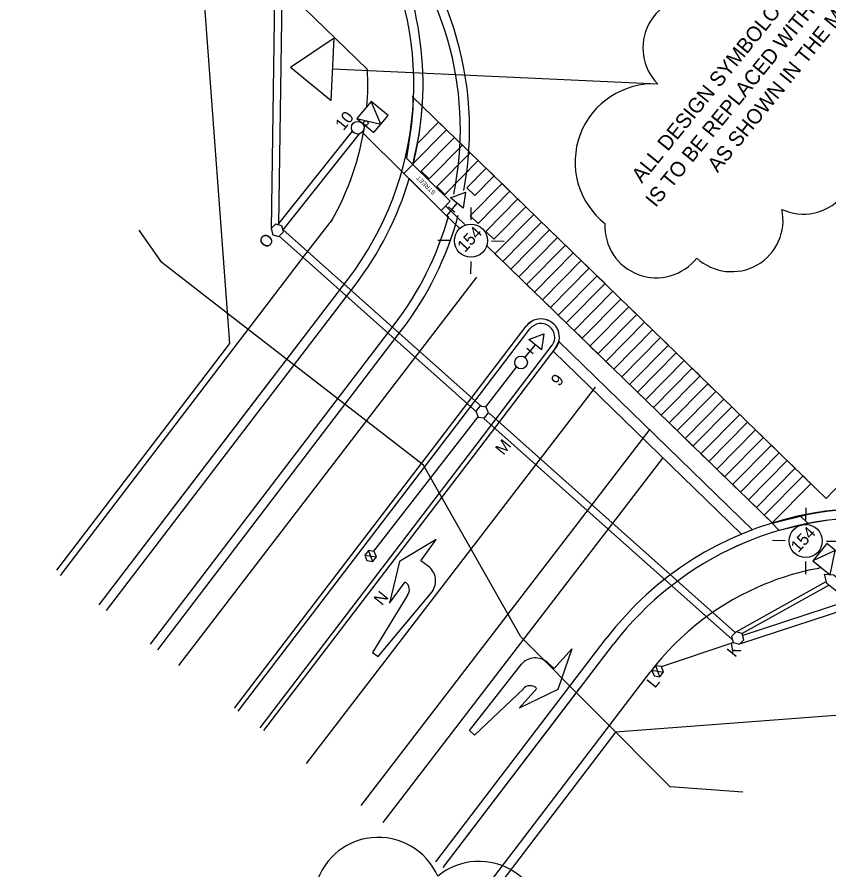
# Model space of a CAD drawing. Extents: x 592613 to 600223, y 4837996 to 4840103.
# Drawn here: x 592734.31 to 592778.42, y 4838979.64 to 4839025.97 of the extents above; entities that cross this region are included whole.
import ezdxf

# ---------------------------------------------------------------- set-up
doc = ezdxf.new("R2010")
doc.units = 0
for name, color, linetype in [('ENG_CURB-BACK', 7, 'Continuous'), ('ENG_CURBSTOP', 7, 'Continuous'), ('ENG_EPAVT', 7, 'Continuous'), ('ENG_LANEWAY', 7, 'Continuous'), ('ENG_LIMITS', 7, 'Continuous'), ('ENG_SH_RIPRAP', 7, 'Continuous'), ('ENG_SIDEWALK', 7, 'Continuous'), ('ENG_TX_TITLEBLOCK', 7, 'Continuous'), ('Level 1', 7, 'Continuous'), ('Level 12', 7, 'Continuous'), ('Level 9', 7, 'Continuous'), ('PMK_LANE', 7, 'Continuous'), ('ROW_ENG_ROW', 7, 'Continuous'), ('ROW_ENG_ROW BO', 7, 'Continuous'), ('TCS_100mm-NEW', 7, 'Continuous'), ('TCS_50mm-NEW', 7, 'Continuous'), ('TCS_ELEC-CHAMBER-NEW', 7, 'Continuous'), ('TCS_LUMINAIRE-NEW', 7, 'Continuous'), ('TCS_POLE-NEW', 7, 'Continuous'), ('TCS_PUSHBUTTON', 7, 'Continuous'), ('TCS_RADAR', 7, 'Continuous'), ('TCS_SIGN', 7, 'Continuous'), ('TCS_SIGNALHEAD', 7, 'Continuous')]:
    doc.layers.add(name, color=color, linetype=linetype)

msp = doc.modelspace()

# ---------------------------------------------------------------- linework, layer by layer
at = {"layer": 'ENG_CURB-BACK'}
for p, q in [((592738.776, 4838994.031), (592752.277, 4839011.713)), ((592741.558, 4838991.907), (592754.805, 4839009.256)), ((592758.431, 4839004.119), (592762.178, 4839009.026)), ((592759.304, 4839002.791), (592763.387, 4839008.138)), ((592746.327, 4838988.266), (592758.431, 4839004.119)), ((592747.519, 4838987.355), (592759.302, 4839002.787)), ((592757.455, 4838979.77), (592766.716, 4838991.9)), ((592759.442, 4838978.253), (592768.704, 4838990.383))]:
    msp.add_line(p, q, dxfattribs=at)
for centre, radius, start, end in [((592740.896, 4839019.876), 17.5, 348.3699, 40.5041), ((592738.367, 4839022.332), 17.5, 322.6377, 27.9119), ((592740.896, 4839019.876), 17.5, 322.6377, 344.4), ((592762.777, 4839008.574), 0.75, 324.4115, 142.9443), ((592780.625, 4838981.28), 17.5, 62.8455, 116.2063), ((592780.625, 4838981.28), 17.5, 113.9004, 142.6377)]:
    msp.add_arc(centre, radius, start, end, dxfattribs=at)
at = {"layer": 'ENG_CURBSTOP'}
msp.add_line((592777.297, 4838998.461), (592776.864, 4838998.883), dxfattribs=at)
for points in [[(592755.466, 4839018.314), (592755.822, 4839017.968), (592756.153, 4839019.562), (592756.288, 4839020.638), (592756.319, 4839021.125), (592756.319, 4839021.125), (592755.812, 4839021.617), (592755.814, 4839021.672), (592755.814, 4839020.962), (592755.733, 4839020.168)], [(592780.551, 4838998.78), (592779.535, 4838998.746), (592778.397, 4838998.637), (592777.421, 4838998.484), (592775.714, 4838998.071), (592775.331, 4838998.477), (592777.309, 4838998.972), (592777.839, 4838999.063), (592778.295, 4838999.128), (592778.96, 4838999.203), (592779.671, 4838999.255), (592780.218, 4838999.275), (592780.463, 4838999.279)]]:
    msp.add_lwpolyline(points, close=True, dxfattribs=at)
at = {"layer": 'ENG_EPAVT'}
for p, q in [((592739.174, 4838993.727), (592752.674, 4839011.409)), ((592741.956, 4838991.603), (592755.202, 4839008.953)), ((592758.279, 4839004.331), (592761.979, 4839009.177)), ((592759.45, 4839002.57), (592763.555, 4839007.946)), ((592746.128, 4838988.417), (592758.274, 4839004.325)), ((592747.718, 4838987.204), (592759.45, 4839002.57)), ((592757.057, 4838980.073), (592766.319, 4838992.203))]:
    msp.add_line(p, q, dxfattribs=at)
for centre, radius, start, end in [((592740.896, 4839019.876), 18, 349.35, 45.8289), ((592738.367, 4839022.332), 18, 345.9453, 28.6887), ((592738.367, 4839022.332), 18, 322.6377, 343.3725), ((592740.896, 4839019.876), 18, 322.6377, 344.9839), ((592762.775, 4839008.576), 1, 320.9502, 142.7929), ((592762.775, 4839008.576), 1, 320.9502, 142.7929), ((592762.777, 4839008.574), 1, 321.1016, 142.9443), ((592780.625, 4838981.28), 18, 62.5135, 142.6377)]:
    msp.add_arc(centre, radius, start, end, dxfattribs=at)
at = {"layer": 'ENG_LANEWAY'}
for p, q in [((592743.099, 4838990.747), (592759.299, 4839011.849)), ((592750.039, 4838985.418), (592765.735, 4839005.863)), ((592753.014, 4838983.135), (592768.709, 4839003.58)), ((592754.204, 4838982.221), (592769.388, 4839002))]:
    msp.add_line(p, q, dxfattribs=at)
at = {"layer": 'ENG_LIMITS'}
for p, q in [((592749.158, 4839023.247), (592751.537, 4839024.843)), ((592751.381, 4839021.441), (592751.537, 4839024.843)), ((592749.158, 4839023.247), (592751.381, 4839021.441)), ((592769.119, 4839022.334), (592751.459, 4839023.142))]:
    msp.add_line(p, q, dxfattribs=at)
for centre, radius, start, end in [((592771.108, 4839024.295), 2.793, 79.6053, 224.6053), ((592768.882, 4839018.089), 4.252, 86.7923, 231.7923), ((592777.034, 4839018.06), 2.793, 245.2392, 30.2392), ((592773.136, 4839014.931), 2.793, 227.2571, 12.2571), ((592769.041, 4839014.601), 2.793, 176.9654, 321.9654), ((592753.939, 4838977.886), 3.522, 23.5797, 168.5797), ((592759.41, 4838976.578), 3.523, 344.5454, 129.5454)]:
    msp.add_arc(centre, radius, start, end, dxfattribs=at)
at = {"layer": 'ENG_SH_RIPRAP'}
msp.add_lwpolyline([(592773.75, 4838983.869), (592769.802, 4838984.16), (592761.677, 4838992.304), (592756.39, 4839001.633), (592745.737, 4839009.864), (592742.175, 4839012.629), (592740.944, 4839014.402)], dxfattribs=at)
msp.add_lwpolyline([(592773.75, 4838983.869), (592769.802, 4838984.16), (592761.677, 4838992.304), (592756.39, 4839001.633), (592745.737, 4839009.864), (592742.175, 4839012.629), (592740.944, 4839014.402)], dxfattribs=at)
at = {"layer": 'ENG_SIDEWALK'}
for p, q in [((592753.347, 4839023.116), (592727.227, 4839048.491)), ((592749.952, 4839013.028), (592751.442, 4839014.981)), ((592736.673, 4838995.637), (592749.952, 4839013.028)), ((592738.776, 4838994.031), (592748.155, 4839006.314)), ((592757.455, 4838979.77), (592764.893, 4838989.512))]:
    msp.add_line(p, q, dxfattribs=at)
for centre, start, end in [((592738.367, 4839022.332), 355.3661, 2.9955), ((592738.367, 4839022.332), 330.2382, 351.4856), ((592780.625, 4838981.28), 100.1986, 113.33), ((592780.625, 4838981.28), 112.093, 142.6377)]:
    msp.add_arc(centre, 15, start, end, dxfattribs=at)
at = {"layer": 'Level 1'}
msp.add_line((592777.822, 4838996.891), (592777.881, 4838996.843), dxfattribs=at)
at = {"layer": 'Level 12'}
for p, q in [((592757.087, 4838997.598), (592755.094, 4838996.389)), ((592756.241, 4838996.439), (592757.087, 4838997.598)), ((592755.094, 4838996.389), (592754.55, 4838994.122)), ((592756.641, 4838996.147), (592756.241, 4838996.439)), ((592754.55, 4838994.122), (592755.396, 4838995.281)), ((592755.528, 4838994.565), (592753.626, 4838991.449)), ((592753.921, 4838991.233), (592756.859, 4838994.75)), ((592753.626, 4838991.449), (592753.921, 4838991.233)), ((592763.5, 4838990.573), (592764.456, 4838991.643)), ((592764.456, 4838991.643), (592763.692, 4838989.441)), ((592758.897, 4838987.212), (592761.719, 4838990.822)), ((592763.131, 4838990.902), (592763.5, 4838990.573)), ((592761.817, 4838989.483), (592759.17, 4838986.968)), ((592761.59, 4838988.433), (592762.545, 4838989.503)), ((592763.692, 4838989.441), (592761.59, 4838988.433)), ((592759.17, 4838986.968), (592758.897, 4838987.212))]:
    msp.add_line(p, q, dxfattribs=at)
for centre, radius, start, end in [((592756.051, 4838995.339), 1, 323.8506, 53.8728), ((592755.124, 4838994.86), 0.5, 323.8443, 53.8679), ((592762.464, 4838990.157), 1, 48.242, 138.2642), ((592762.19, 4838989.149), 0.5, 48.2469, 138.2706)]:
    msp.add_arc(centre, radius, start, end, dxfattribs=at)
at = {"layer": 'PMK_LANE'}
for p, q in [((592756.327, 4839021.131), (592778.275, 4838999.816)), ((592778.275, 4838999.816), (592797.765, 4839020.444)), ((592757.215, 4839020.268), (592756.078, 4839019.116)), ((592757.646, 4839019.85), (592757.215, 4839020.268)), ((592755.845, 4839018.026), (592757.646, 4839019.85)), ((592758.076, 4839019.432), (592756.267, 4839017.6)), ((592758.507, 4839019.014), (592758.076, 4839019.432)), ((592756.698, 4839017.182), (592758.507, 4839019.014)), ((592758.937, 4839018.596), (592757.123, 4839016.758)), ((592759.368, 4839018.178), (592758.937, 4839018.596)), ((592757.553, 4839016.34), (592759.368, 4839018.178)), ((592759.798, 4839017.76), (592758.744, 4839016.693)), ((592760.228, 4839017.342), (592759.798, 4839017.76)), ((592756.267, 4839017.6), (592756.698, 4839017.182)), ((592759.175, 4839016.274), (592760.228, 4839017.342)), ((592757.123, 4839016.758), (592757.553, 4839016.34)), ((592760.659, 4839016.924), (592758.924, 4839015.167)), ((592761.089, 4839016.506), (592760.659, 4839016.924)), ((592758.744, 4839016.693), (592759.175, 4839016.274)), ((592759.355, 4839014.749), (592761.089, 4839016.506)), ((592761.52, 4839016.088), (592759.781, 4839014.326)), ((592761.95, 4839015.67), (592761.52, 4839016.088)), ((592757.596, 4839015.716), (592758.672, 4839014.671)), ((592760.211, 4839013.908), (592761.95, 4839015.67)), ((592758.924, 4839015.167), (592759.355, 4839014.749)), ((592762.381, 4839015.252), (592760.273, 4839013.117)), ((592762.811, 4839014.834), (592762.381, 4839015.252)), ((592760.703, 4839012.699), (592762.811, 4839014.834)), ((592763.242, 4839014.416), (592761.134, 4839012.281)), ((592763.672, 4839013.998), (592763.242, 4839014.416)), ((592759.781, 4839014.326), (592760.211, 4839013.908)), ((592761.564, 4839011.863), (592763.672, 4839013.998)), ((592759.828, 4839013.549), (592775.338, 4838998.486)), ((592764.102, 4839013.58), (592761.995, 4839011.445)), ((592764.533, 4839013.162), (592764.102, 4839013.58)), ((592760.273, 4839013.117), (592760.703, 4839012.699)), ((592762.425, 4839011.027), (592764.533, 4839013.162)), ((592764.963, 4839012.744), (592762.855, 4839010.609)), ((592765.394, 4839012.326), (592764.963, 4839012.744)), ((592761.134, 4839012.281), (592761.564, 4839011.863)), ((592763.286, 4839010.191), (592765.394, 4839012.326)), ((592765.824, 4839011.908), (592763.716, 4839009.773)), ((592766.255, 4839011.49), (592765.824, 4839011.908)), ((592761.995, 4839011.445), (592762.425, 4839011.027)), ((592764.147, 4839009.355), (592766.255, 4839011.49)), ((592766.685, 4839011.072), (592764.577, 4839008.937)), ((592767.115, 4839010.653), (592766.685, 4839011.072)), ((592762.855, 4839010.609), (592763.286, 4839010.191)), ((592765.008, 4839008.519), (592767.115, 4839010.653)), ((592767.546, 4839010.235), (592765.438, 4839008.101)), ((592767.976, 4839009.817), (592767.546, 4839010.235)), ((592763.716, 4839009.773), (592764.147, 4839009.355)), ((592765.869, 4839007.683), (592767.976, 4839009.817)), ((592768.407, 4839009.399), (592766.299, 4839007.265)), ((592768.837, 4839008.981), (592768.407, 4839009.399)), ((592764.577, 4839008.937), (592765.008, 4839008.519)), ((592766.729, 4839006.846), (592768.837, 4839008.981)), ((592769.268, 4839008.563), (592767.16, 4839006.428)), ((592769.698, 4839008.145), (592769.268, 4839008.563)), ((592763.751, 4839008.345), (592774.276, 4838998.123)), ((592765.438, 4839008.101), (592765.869, 4839007.683)), ((592767.59, 4839006.01), (592769.698, 4839008.145)), ((592763.447, 4839007.804), (592773.666, 4838997.88)), ((592770.129, 4839007.727), (592768.021, 4839005.592)), ((592770.559, 4839007.309), (592770.129, 4839007.727)), ((592766.299, 4839007.265), (592766.729, 4839006.846)), ((592768.451, 4839005.174), (592770.559, 4839007.309)), ((592770.989, 4839006.891), (592768.882, 4839004.756)), ((592771.42, 4839006.473), (592770.989, 4839006.891)), ((592767.16, 4839006.428), (592767.59, 4839006.01)), ((592769.312, 4839004.338), (592771.42, 4839006.473)), ((592771.85, 4839006.055), (592769.743, 4839003.92)), ((592770.173, 4839003.502), (592772.281, 4839005.637)), ((592772.281, 4839005.637), (592771.85, 4839006.055)), ((592768.021, 4839005.592), (592768.451, 4839005.174)), ((592772.711, 4839005.219), (592770.603, 4839003.084)), ((592773.142, 4839004.801), (592772.711, 4839005.219)), ((592768.882, 4839004.756), (592769.312, 4839004.338)), ((592771.034, 4839002.666), (592773.142, 4839004.801)), ((592773.572, 4839004.383), (592771.464, 4839002.248)), ((592774.002, 4839003.965), (592773.572, 4839004.383)), ((592769.743, 4839003.92), (592770.173, 4839003.502)), ((592771.895, 4839001.83), (592774.002, 4839003.965)), ((592774.433, 4839003.547), (592772.325, 4839001.412)), ((592774.863, 4839003.129), (592774.433, 4839003.547)), ((592770.603, 4839003.084), (592771.034, 4839002.666)), ((592772.756, 4839000.994), (592774.863, 4839003.129)), ((592775.294, 4839002.711), (592773.186, 4839000.576)), ((592775.724, 4839002.293), (592775.294, 4839002.711)), ((592771.464, 4839002.248), (592771.895, 4839001.83)), ((592773.616, 4839000.158), (592775.724, 4839002.293)), ((592776.155, 4839001.875), (592774.047, 4838999.74)), ((592774.477, 4838999.322), (592776.585, 4839001.457)), ((592776.585, 4839001.457), (592776.155, 4839001.875)), ((592772.325, 4839001.412), (592772.756, 4839000.994)), ((592777.016, 4839001.039), (592774.908, 4838998.904)), ((592777.446, 4839000.621), (592777.016, 4839001.039)), ((592773.186, 4839000.576), (592773.616, 4839000.158)), ((592775.338, 4838998.486), (592777.446, 4839000.621)), ((592774.047, 4838999.74), (592774.477, 4838999.322)), ((592774.908, 4838998.904), (592775.338, 4838998.486))]:
    msp.add_line(p, q, dxfattribs=at)
msp.add_lwpolyline([(592763.447, 4839007.804), (592763.751, 4839008.345), (592774.276, 4838998.123), (592773.666, 4838997.88)], close=True, dxfattribs=at)
msp.add_arc((592738.367, 4839022.332), 18, 346.1571, 349.7059, dxfattribs=at)
at = {"layer": 'ROW_ENG_ROW'}
for p, q in [((592744.202, 4839030.606), (592745.857, 4839008.239)), ((592787.344, 4838988.695), (592766.831, 4838987.113))]:
    msp.add_line(p, q, dxfattribs=at)
at = {"layer": 'ROW_ENG_ROW BO'}
for p, q in [((592745.857, 4839008.239), (592736.457, 4838995.927)), ((592766.831, 4838987.113), (592759.571, 4838977.605))]:
    msp.add_line(p, q, dxfattribs=at)
at = {"layer": 'TCS_100mm-NEW'}
for p, q in [((592748.38, 4839032.901), (592748.111, 4839014.474)), ((592748.476, 4839014.69), (592752.534, 4839019.781)), ((592748.541, 4839014.079), (592759.289, 4839004.51)), ((592759.777, 4839004.798), (592761.444, 4839006.958)), ((592759.677, 4839004.164), (592773.185, 4838992.138)), ((592773.628, 4838991.931), (592785.366, 4838995.786)), ((592778.405, 4838995.097), (592773.714, 4838992.478))]:
    msp.add_line(p, q, dxfattribs=at)
at = {"layer": 'TCS_50mm-NEW'}
for p, q in [((592748.766, 4839032.728), (592748.515, 4839014.698)), ((592748.77, 4839014.416), (592752.92, 4839019.624)), ((592748.756, 4839014.423), (592759.54, 4839004.822)), ((592753.698, 4838996.956), (592759.36, 4839004.255)), ((592759.965, 4839004.444), (592773.315, 4838992.558)), ((592773.715, 4838992.381), (592785.24, 4838996.166)), ((592773.38, 4838992.567), (592778.276, 4838995.311)), ((592769.323, 4838990.683), (592773.225, 4838991.989))]:
    msp.add_line(p, q, dxfattribs=at)
at = {"layer": 'TCS_ELEC-CHAMBER-NEW'}
for p, q in [((592748.355, 4839014.722), (592748.11, 4839014.478)), ((592748.11, 4839014.478), (592748.2, 4839014.144)), ((592748.688, 4839014.633), (592748.355, 4839014.722)), ((592748.778, 4839014.299), (592748.688, 4839014.633)), ((592748.2, 4839014.144), (592748.534, 4839014.054)), ((592748.534, 4839014.054), (592748.778, 4839014.299)), ((592759.448, 4839004.831), (592759.238, 4839004.557)), ((592759.791, 4839004.785), (592759.448, 4839004.831)), ((592759.923, 4839004.466), (592759.791, 4839004.785)), ((592759.238, 4839004.557), (592759.37, 4839004.237)), ((592759.37, 4839004.237), (592759.712, 4839004.192)), ((592759.712, 4839004.192), (592759.923, 4839004.466)), ((592753.405, 4838996.994), (592753.204, 4838996.746)), ((592753.634, 4838996.398), (592753.405, 4838996.994)), ((592753.72, 4838996.944), (592753.405, 4838996.994)), ((592753.834, 4838996.646), (592753.72, 4838996.944)), ((592753.204, 4838996.746), (592753.834, 4838996.646)), ((592753.204, 4838996.746), (592753.319, 4838996.448)), ((592753.319, 4838996.448), (592753.634, 4838996.398)), ((592753.634, 4838996.398), (592753.834, 4838996.646)), ((592773.38, 4838992.567), (592773.136, 4838992.323)), ((592773.136, 4838992.323), (592773.225, 4838991.989)), ((592773.714, 4838992.478), (592773.38, 4838992.567)), ((592773.803, 4838992.144), (592773.714, 4838992.478)), ((592773.225, 4838991.989), (592773.559, 4838991.9)), ((592773.559, 4838991.9), (592773.803, 4838992.144)), ((592769.008, 4838990.732), (592768.807, 4838990.484)), ((592768.807, 4838990.484), (592769.437, 4838990.385)), ((592768.807, 4838990.484), (592768.922, 4838990.187)), ((592769.237, 4838990.137), (592769.008, 4838990.732)), ((592769.323, 4838990.683), (592769.008, 4838990.732)), ((592769.237, 4838990.137), (592769.437, 4838990.385)), ((592769.437, 4838990.385), (592769.323, 4838990.683)), ((592768.922, 4838990.187), (592769.237, 4838990.137))]:
    msp.add_line(p, q, dxfattribs=at)
at = {"layer": 'TCS_LUMINAIRE-NEW'}
for p, q in [((592753.067, 4839019.714), (592755.382, 4839017.42)), ((592755.61, 4839017.194), (592757.643, 4839015.18)), ((592758.981, 4839014.947), (592758.988, 4839015.622)), ((592757.643, 4839015.179), (592758.368, 4839014.491)), ((592757.846, 4839013.833), (592757.17, 4839013.84)), ((592760.095, 4839013.811), (592760.77, 4839013.804)), ((592758.959, 4839012.698), (592758.952, 4839012.022)), ((592777.171, 4838998.634), (592777.178, 4838999.31)), ((592776.036, 4838997.521), (592775.36, 4838997.528)), ((592778.284, 4838997.499), (592778.96, 4838997.492)), ((592777.149, 4838996.385), (592777.142, 4838995.71))]:
    msp.add_line(p, q, dxfattribs=at)
for centre in [(592758.97, 4839013.822), (592777.16, 4838997.51)]:
    msp.add_circle(centre, 0.9, dxfattribs=at)
at = {"layer": 'TCS_POLE-NEW'}
for centre in [(592752.821, 4839019.956), (592761.696, 4839007.206)]:
    msp.add_circle(centre, 0.346, dxfattribs=at)
at = {"layer": 'TCS_PUSHBUTTON'}
msp.add_circle((592753.258, 4839020.214), 0.12, dxfattribs=at)
at = {"layer": 'TCS_RADAR'}
msp.add_lwpolyline([(592779.221, 4838995.224), (592778.847, 4838994.763), (592778.304, 4838995.204), (592778.174, 4838995.702), (592778.679, 4838995.664)], close=True, dxfattribs=at)
at = {"layer": 'TCS_SIGN'}
msp.add_lwpolyline([(592757.349, 4839015.466), (592755.326, 4839017.467), (592755.822, 4839017.968), (592757.844, 4839015.967)], close=True, dxfattribs=at)
at = {"layer": 'TCS_SIGNALHEAD'}
for p, q in [((592754.465, 4839020.622), (592753.543, 4839021.39)), ((592752.775, 4839020.468), (592753.696, 4839019.7)), ((592753.696, 4839019.7), (592754.465, 4839020.622)), ((592757.858, 4839016.143), (592758.682, 4839016.458)), ((592758.682, 4839016.458), (592758.542, 4839015.586)), ((592758.2, 4839015.865), (592757.643, 4839015.18)), ((592758.542, 4839015.586), (592757.858, 4839016.143)), ((592757.921, 4839015.522), (592757.75, 4839015.661)), ((592757.921, 4839015.522), (592758.093, 4839015.383)), ((592762.113, 4839008.451), (592762.937, 4839008.766)), ((592762.797, 4839007.894), (592762.113, 4839008.451)), ((592762.937, 4839008.766), (592762.797, 4839007.894)), ((592762.455, 4839008.173), (592761.898, 4839007.487)), ((592762.176, 4839007.83), (592762.005, 4839007.969)), ((592762.176, 4839007.83), (592762.347, 4839007.691)), ((592778.303, 4838997.363), (592777.548, 4838996.429)), ((592779.236, 4838996.608), (592778.303, 4838997.363))]:
    msp.add_line(p, q, dxfattribs=at)
for points in [[(592753.543, 4839021.39), (592752.775, 4839020.468), (592754.081, 4839020.161), (592754.081, 4839020.161)], [(592758.542, 4839015.586), (592757.858, 4839016.143), (592758.682, 4839016.458), (592758.682, 4839016.458)], [(592762.797, 4839007.894), (592762.113, 4839008.451), (592762.937, 4839008.766), (592762.937, 4839008.766)], [(592777.548, 4838996.429), (592778.482, 4838995.675), (592778.769, 4838996.986), (592778.769, 4838996.986)]]:
    msp.add_lwpolyline(points, close=True, dxfattribs=at)

# ---------------------------------------------------------------- texts
at = {"layer": 'ENG_TX_TITLEBLOCK'}
for s, p in [('IS TO BE REPLACED WITH EXISTING SYMBOLOGY ', (592769.012, 4839015.586)), ('ALL DESIGN SYMBOLOGY ON THE MAIN PLAN', (592768.256, 4839016.906)), ('AS SHOWN IN THE MAIN LEGEND.', (592772.376, 4839017.477))]:
    msp.add_text(s, height=0.81055, rotation=50.9012, dxfattribs=at).set_placement(p)
at = {"layer": 'Level 9'}
msp.add_text('154', height=0.65, rotation=47.2608, dxfattribs=at).set_placement((592758.644, 4839013.155))
at = {"layer": 'TCS_ELEC-CHAMBER-NEW'}
for s, p in [('O', (592747.892, 4839013.356)), ('M', (592760.738, 4839002.132)), ('N', (592754.136, 4838993.963)), ('K', (592773.323, 4838991.147)), ('L', (592768.966, 4838989.471))]:
    msp.add_text(s, height=0.65, rotation=51.0574, dxfattribs=at).set_placement(p)
at = {"layer": 'TCS_LUMINAIRE-NEW'}
for p in [(592758.641, 4839013.159), (592776.76, 4838996.849)]:
    msp.add_text('154', height=0.65, rotation=47.2608, dxfattribs=at).set_placement(p)
at = {"layer": 'TCS_POLE-NEW'}
for s, p in [('10', (592752.042, 4839019.765)), ('9', (592763.76, 4839005.871))]:
    msp.add_text(s, height=0.65, rotation=51.0574, dxfattribs=at).set_placement(p)
at = {"layer": 'TCS_SIGN'}
msp.add_text('STREET', height=0.2407, rotation=135.3025, dxfattribs=at).set_placement((592757.077, 4839016.457))

doc.saveas('drawing.dxf')
